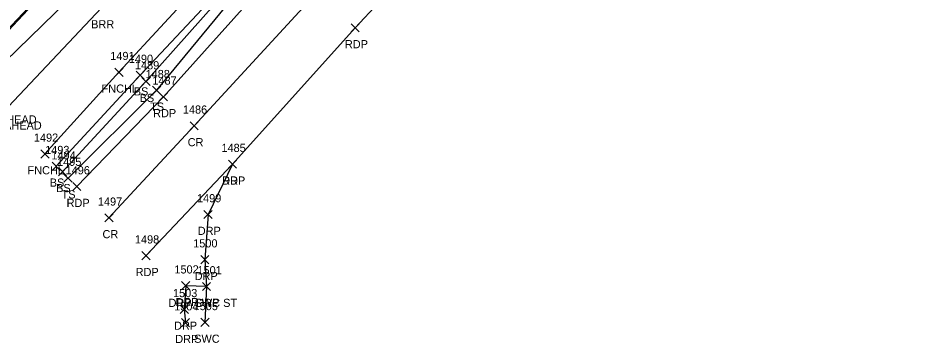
# Model space of a CAD drawing. Extents: x 1688195 to 1692013, y 424605 to 441234.
# Drawn here: x 1691404.7 to 1691624.9, y 438816.8 to 438896.5 of the extents above; entities that cross this region are included whole.
import ezdxf

# ---------------------------------------------------------------- set-up
doc = ezdxf.new("R2010")
doc.units = 0
for name, color, linetype in [('L_A', 7, 'Continuous'), ('L_I', 7, 'Continuous'), ('L_TIC', 7, 'Continuous'), ('LABL', 7, 'Continuous'), ('LELB', 7, 'Continuous'), ('LFNC', 7, 'Continuous'), ('P_A', 7, 'Continuous'), ('P_I', 7, 'Continuous'), ('P_TIC', 7, 'Continuous'), ('PET', 7, 'Continuous'), ('PRC', 7, 'Continuous'), ('R_A', 7, 'Continuous'), ('R_I', 7, 'Continuous'), ('R_TIC', 7, 'Continuous'), ('RDP', 7, 'Continuous'), ('RGR', 7, 'Continuous'), ('RSW', 7, 'Continuous'), ('S_C', 7, 'Continuous')]:
    doc.layers.add(name, color=color, linetype=linetype)

msp = doc.modelspace()

# ---------------------------------------------------------------- linework, layer by layer
at = {"layer": 'L_TIC'}
for points in [[(1691428.39, 438882.14), (1691430.39, 438884.14)], [(1691430.39, 438882.14), (1691428.39, 438884.14)], [(1691433.59, 438881.45), (1691435.59, 438883.45)], [(1691435.59, 438881.45), (1691433.59, 438883.45)], [(1691435.02, 438879.86), (1691437.02, 438881.86)], [(1691437.02, 438879.86), (1691435.02, 438881.86)], [(1691437.62, 438877.72), (1691439.62, 438879.72)], [(1691439.62, 438877.72), (1691437.62, 438879.72)], [(1691410.26, 438862.12), (1691412.26, 438864.12)], [(1691412.26, 438862.12), (1691410.26, 438864.12)], [(1691413.01, 438859.1), (1691415.01, 438861.1)], [(1691415.01, 438859.1), (1691413.01, 438861.1)], [(1691414.55, 438857.76), (1691416.55, 438859.76)], [(1691416.55, 438857.76), (1691414.55, 438859.76)], [(1691415.93, 438856.19), (1691417.93, 438858.19)], [(1691417.93, 438856.19), (1691415.93, 438858.19)]]:
    msp.add_lwpolyline(points, dxfattribs=at)
at = {"layer": 'LABL'}
msp.add_lwpolyline([(1691400.95, 438873.28), (1691425.11, 438898.91), (1691453.29, 438927.69), (1691482.15, 438955.08), (1691490.49, 438956.17)], dxfattribs=at)
at = {"layer": 'LELB'}
for points in [[(1691867.08, 439165.21), (1691844.95, 439160.27), (1691798.84, 439152.11), (1691745.51, 439147.11), (1691728.71, 439142.4), (1691709.09, 439133.88), (1691683, 439117.2), (1691643.28, 439091.08), (1691604.89, 439061.29), (1691572.53, 439026.72), (1691542.38, 438995.55), (1691505.84, 438957.5), (1691487.66, 438936.34), (1691466.81, 438915.54), (1691436.02, 438880.86), (1691415.55, 438858.76)], [(1691604.89, 439061.29), (1691570.2, 439029.58), (1691540.68, 438997.55), (1691504.19, 438958.83), (1691485.94, 438937.8), (1691466.29, 438916.24), (1691434.59, 438882.45), (1691414.01, 438860.1)], [(1691395.27, 438879.71), (1691419.93, 438903.79), (1691447.01, 438933.65), (1691476.59, 438966.16), (1691497.62, 438986.55)], [(1691468.3, 438914.89), (1691438.62, 438878.72), (1691416.93, 438857.19)]]:
    msp.add_lwpolyline(points, dxfattribs=at)
at = {"layer": 'LFNC'}
msp.add_lwpolyline([(1691844.63, 439219.19), (1691827.3, 439208.18), (1691808.98, 439197.07), (1691805.18, 439194.78), (1691802.65, 439193.15), (1691780.93, 439179.95), (1691740.49, 439155.55), (1691707.63, 439134.9), (1691682.09, 439120.04), (1691638.96, 439093.47), (1691599.84, 439067.34), (1691566.38, 439033.38), (1691536.95, 439001.22), (1691500.89, 438961.26), (1691462.91, 438919.55), (1691429.39, 438883.14), (1691411.26, 438863.12)], dxfattribs=at)
at = {"layer": 'P_TIC'}
for points in [[(1691486.26, 438893.03), (1691488.26, 438895.03)], [(1691488.26, 438893.03), (1691486.26, 438895.03)], [(1691439.28, 438876.12), (1691441.28, 438878.12)], [(1691441.28, 438876.12), (1691439.28, 438878.12)], [(1691446.81, 438869), (1691448.81, 438871)], [(1691448.81, 438869), (1691446.81, 438871)], [(1691456.21, 438859.6), (1691458.21, 438861.6)], [(1691458.21, 438859.6), (1691456.21, 438861.6)], [(1691418.08, 438854.12), (1691420.08, 438856.12)], [(1691420.08, 438854.12), (1691418.08, 438856.12)], [(1691425.94, 438846.45), (1691427.94, 438848.45)], [(1691427.94, 438846.45), (1691425.94, 438848.45)], [(1691435.01, 438837.17), (1691437.01, 438839.17)], [(1691437.01, 438837.17), (1691435.01, 438839.17)]]:
    msp.add_lwpolyline(points, dxfattribs=at)
at = {"layer": 'PET'}
for points in [[(1691392.15, 438883.12), (1691415.43, 438907.79), (1691443.51, 438937.17), (1691473.2, 438969.34), (1691494.19, 438991.98), (1691527.98, 439028.02), (1691561.01, 439063.43)], [(1691620.88, 439044.07), (1691602.22, 439033.1), (1691579.03, 439017.01), (1691566.59, 439007.7), (1691551.73, 438994.67), (1691535.43, 438978.91), (1691510.19, 438952.85), (1691471.21, 438911.57), (1691440.28, 438877.12), (1691419.08, 438855.12)], [(1691672.86, 439042.9), (1691649.54, 439032.89), (1691634.02, 439024.76), (1691613.34, 439012.41), (1691591.31, 438997.78), (1691582.05, 438990.56), (1691567.39, 438977.9), (1691551.1, 438962.07), (1691527.82, 438937.62), (1691487.26, 438894.03), (1691457.21, 438860.6), (1691436.01, 438838.17)]]:
    msp.add_lwpolyline(points, dxfattribs=at)
at = {"layer": 'PRC'}
msp.add_lwpolyline([(1691888.13, 439193.66), (1691921.53, 439164.99), (1691933.61, 439155.1), (1691905.33, 439143.8), (1691864.7, 439127.18), (1691822.78, 439112.3), (1691787.26, 439099.58), (1691756.92, 439088.3), (1691729.19, 439077.85), (1691704.03, 439068.3), (1691667.7, 439053.5), (1691645.71, 439043.49), (1691628.46, 439034.88), (1691608.73, 439022.92), (1691585.22, 439006.39), (1691574.92, 438998.75), (1691559.84, 438985.93), (1691543.5, 438970.76), (1691518.61, 438946.02), (1691478.27, 438903.21), (1691447.81, 438870), (1691426.94, 438847.45)], dxfattribs=at)
at = {"layer": 'R_TIC'}
for points in [[(1691456.21, 438859.6), (1691458.21, 438861.6)], [(1691458.21, 438859.6), (1691456.21, 438861.6)], [(1691450.22, 438847.27), (1691452.22, 438849.27)], [(1691452.22, 438847.27), (1691450.22, 438849.27)], [(1691449.45, 438836.2), (1691451.45, 438838.2)], [(1691451.45, 438836.2), (1691449.45, 438838.2)], [(1691444.76, 438829.81), (1691446.76, 438831.81)], [(1691446.76, 438829.81), (1691444.76, 438831.81)], [(1691449.83, 438829.61), (1691451.83, 438831.61)], [(1691451.83, 438829.61), (1691449.83, 438831.61)], [(1691449.83, 438829.61), (1691451.83, 438831.61)], [(1691451.83, 438829.61), (1691449.83, 438831.61)], [(1691444.41, 438824.01), (1691446.41, 438826.01)], [(1691446.41, 438824.01), (1691444.41, 438826.01)], [(1691444.7, 438820.76), (1691446.7, 438822.76)], [(1691446.7, 438820.76), (1691444.7, 438822.76)], [(1691449.46, 438820.82), (1691451.46, 438822.82)], [(1691451.46, 438820.82), (1691449.46, 438822.82)]]:
    msp.add_lwpolyline(points, dxfattribs=at)
at = {"layer": 'RDP'}
msp.add_lwpolyline([(1691457.21, 438860.6), (1691451.22, 438848.27), (1691450.45, 438837.2), (1691450.83, 438830.61), (1691445.76, 438830.81), (1691445.41, 438825.01), (1691445.7, 438821.76)], dxfattribs=at)
at = {"layer": 'RGR'}
msp.add_lwpolyline([(1691392.43, 438882.91), (1691415.63, 438907.66), (1691443.42, 438937.01), (1691473.56, 438969.15), (1691494.4, 438991.79), (1691528.19, 439027.86), (1691561.17, 439063.3), (1691590.77, 439094.95), (1691620.16, 439126.42), (1691638.64, 439146.14), (1691654.09, 439162.7)], dxfattribs=at)
at = {"layer": 'RSW'}
msp.add_lwpolyline([(1691450.83, 438830.61), (1691450.46, 438821.82)], dxfattribs=at)

# ---------------------------------------------------------------- texts
at = {"layer": 'L_A'}
for s, p in [('BRR', (1691422.59, 438893.91)), ('FNCHL', (1691425.14, 438878.14)), ('BS', (1691433.03, 438877.45)), ('BS', (1691434.46, 438875.86)), ('TS', (1691437.03, 438873.72)), ('FNCHL', (1691407, 438858.12)), ('BS', (1691412.45, 438855.1)), ('BS', (1691413.99, 438853.76)), ('TS', (1691415.34, 438852.19))]:
    msp.add_text(s, height=2, dxfattribs=at).set_placement(p)
at = {"layer": 'L_I'}
for s, p in [('1491', (1691427.27, 438886.14)), ('1490', (1691431.81, 438885.45)), ('1489', (1691433.32, 438883.86)), ('1488', (1691435.93, 438881.72)), ('1492', (1691408.56, 438866.12)), ('1493', (1691411.32, 438863.1)), ('1494', (1691412.86, 438861.76)), ('1495', (1691414.24, 438860.19))]:
    msp.add_text(s, height=2, dxfattribs=at).set_placement(p)
at = {"layer": 'P_A'}
for s, p in [('RDP', (1691484.75, 438889.03)), ('RDP', (1691437.77, 438872.12)), ('CR', (1691446.24, 438865)), ('RDP', (1691454.69, 438855.6)), ('RDP', (1691416.57, 438850.12)), ('CR', (1691425.37, 438842.45)), ('RDP', (1691433.49, 438833.17))]:
    msp.add_text(s, height=2, dxfattribs=at).set_placement(p)
at = {"layer": 'P_I'}
for s, p in [('1487', (1691437.59, 438880.12)), ('1486', (1691445.06, 438873)), ('1485', (1691454.51, 438863.6)), ('1496', (1691416.33, 438858.12)), ('1497', (1691424.24, 438850.45)), ('1498', (1691433.31, 438841.17))]:
    msp.add_text(s, height=2, dxfattribs=at).set_placement(p)
at = {"layer": 'R_A'}
for s, p in [('DRP', (1691454.69, 438855.6)), ('DRP', (1691448.71, 438843.27)), ('DRP', (1691447.94, 438832.2)), ('DRP SWC ST', (1691441.55, 438825.61)), ('DRP', (1691443.24, 438825.81)), ('DRP', (1691448.32, 438825.61)), ('DRP', (1691442.9, 438820.01)), ('DRP', (1691443.19, 438816.76)), ('SWC', (1691447.83, 438816.82))]:
    msp.add_text(s, height=2, dxfattribs=at).set_placement(p)
at = {"layer": 'R_I'}
for s, p in [('1485', (1691454.51, 438863.6)), ('1499', (1691448.52, 438851.27)), ('1500', (1691447.59, 438840.2)), ('1502', (1691442.98, 438833.81)), ('1501', (1691448.63, 438833.61)), ('1501', (1691448.63, 438833.61)), ('1503', (1691442.64, 438828.01)), ('1504', (1691442.93, 438824.76)), ('1505', (1691447.69, 438824.82))]:
    msp.add_text(s, height=2, dxfattribs=at).set_placement(p)
at = {"layer": 'S_C'}
for p in [(1691379.36, 438870.57), (1691380.61, 438869.11)]:
    msp.add_text('TRAFFIC LIGHT AHEAD', height=2, dxfattribs=at).set_placement(p)

doc.saveas('drawing.dxf')
